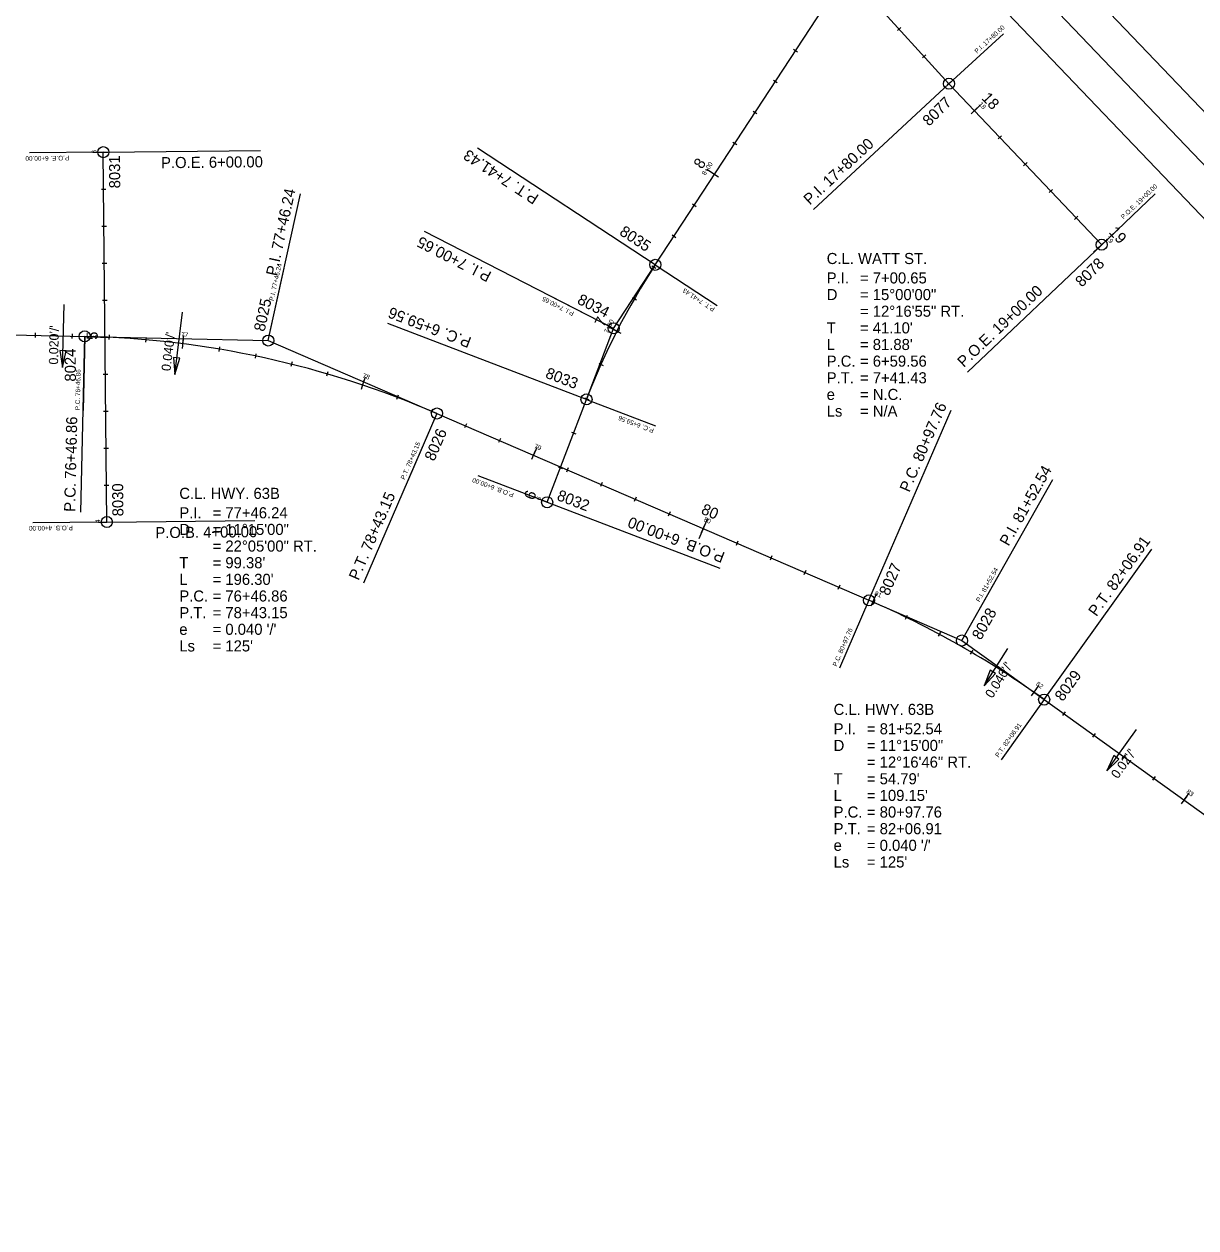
# Model space of a CAD drawing. Extents: x 1708585 to 1714116, y 541444 to 545437.
# Drawn here: x 1712182 to 1712816, y 542879 to 543530 of the extents above; entities that cross this region are included whole.
import ezdxf

# ---------------------------------------------------------------- set-up
doc = ezdxf.new("R2010")
doc.units = 0
for name, color, linetype in [('CL_Highway_2', 7, 'Continuous'), ('CL_Highway_2_40_PText', 7, 'Continuous'), ('CL_Highway_2_40_Sta', 7, 'Continuous'), ('CL_Highway_2_PText', 7, 'Continuous'), ('CL_Highway_2_Sta', 7, 'Continuous'), ('CL_Highway_2_Tangent', 7, 'Continuous'), ('CL_Railroad', 7, 'Continuous'), ('CL_XS_1', 7, 'Continuous'), ('CL_XS_1_40_PText', 7, 'Continuous'), ('CL_XS_1_40_Sta', 7, 'Continuous'), ('CL_XS_1_PText', 7, 'Continuous'), ('CL_XS_1_Sta', 7, 'Continuous'), ('CL_XS_1_Sta_Minor_Text', 7, 'Continuous'), ('CL_XS_1_Tangent', 7, 'Continuous'), ('CL_XS_2', 7, 'Continuous'), ('CL_XS_2_40_PText', 7, 'Continuous'), ('CL_XS_2_40_Sta', 7, 'Continuous'), ('CL_XS_2_PText', 7, 'Continuous'), ('CL_XS_2_Sta', 7, 'Continuous'), ('CL_XS_3', 7, 'Continuous'), ('CL_XS_3_40_PText', 7, 'Continuous'), ('CL_XS_3_40_Sta', 7, 'Continuous'), ('CL_XS_3_PText', 7, 'Continuous'), ('CL_XS_3_Sta', 7, 'Continuous'), ('CL_XS_3_Sta_Minor_Text', 7, 'Continuous'), ('CurveData_100', 7, 'Continuous'), ('Point_CL_Highway_2', 7, 'Continuous'), ('Point_CL_XS_1', 7, 'Continuous'), ('Point_CL_XS_2', 7, 'Continuous'), ('Point_CL_XS_3', 7, 'Continuous'), ('Point_Number', 7, 'Continuous'), ('R_SE_Slope', 7, 'Continuous')]:
    doc.layers.add(name, color=color, linetype=linetype)

msp = doc.modelspace()

# ---------------------------------------------------------------- linework, layer by layer
at = {"layer": 'CL_Highway_2'}
for p, q in [((1712066.88, 543364.6), (1712214.97, 543361.25)), ((1712405.55, 543319.57), (1712639.25, 543218.55)), ((1712734.05, 543164.87), (1712890.94, 543052.31))]:
    msp.add_line(p, q, dxfattribs=at)
for centre, start, end in [((1712203.46, 542852.08), 66.62237, 88.70571), ((1712437.17, 542751.06), 54.3428, 66.62237)]:
    msp.add_arc(centre, 509.3, start, end, dxfattribs=at)
at = {"layer": 'CL_Highway_2_40_PText'}
for points in [[(1712314.32, 543359.01), (1712322.87, 543398.08)], [(1712214.97, 543361.25), (1712214.06, 543321.26)], [(1712405.55, 543319.57), (1712389.67, 543282.86)], [(1712689.54, 543196.81), (1712709.25, 543231.62)], [(1712639.25, 543218.55), (1712623.38, 543181.83)], [(1712734.05, 543164.87), (1712710.73, 543132.37)]]:
    msp.add_lwpolyline(points, dxfattribs=at)
at = {"layer": 'CL_Highway_2_40_Sta'}
for points in [[(1712188.15, 543363.11), (1712188.09, 543360.61)], [(1712208.14, 543362.66), (1712208.08, 543360.16)], [(1712228.16, 543362.03), (1712228.04, 543359.54)], [(1712248.16, 543360.67), (1712247.95, 543358.18)], [(1712268.25, 543359.76), (1712267.62, 543354.8)], [(1712287.93, 543355.59), (1712287.52, 543353.13)], [(1712307.63, 543351.89), (1712307.12, 543349.44)], [(1712327.17, 543347.42), (1712326.57, 543344.99)], [(1712346.53, 543342.18), (1712345.82, 543339.78)], [(1712366.05, 543337.37), (1712364.46, 543332.63)], [(1712384.54, 543329.44), (1712383.65, 543327.1)], [(1712403.14, 543321.96), (1712402.16, 543319.66)], [(1712421.51, 543314.03), (1712420.51, 543311.74)], [(1712439.87, 543306.1), (1712438.87, 543303.8)], [(1712458.72, 543299.31), (1712456.74, 543294.72)], [(1712476.58, 543290.23), (1712475.59, 543287.93)], [(1712494.94, 543282.29), (1712493.95, 543280)], [(1712513.3, 543274.36), (1712512.31, 543272.06)], [(1712531.66, 543266.42), (1712530.66, 543264.13)], [(1712550.51, 543259.63), (1712548.53, 543255.04)], [(1712568.37, 543250.55), (1712567.38, 543248.25)], [(1712586.73, 543242.61), (1712585.74, 543240.32)], [(1712605.09, 543234.68), (1712604.1, 543232.38)], [(1712623.45, 543226.74), (1712622.45, 543224.45)], [(1712642.31, 543219.94), (1712640.31, 543215.36)], [(1712660.01, 543210.4), (1712658.92, 543208.15)], [(1712677.88, 543201.3), (1712676.7, 543199.1)], [(1712695.37, 543191.5), (1712694.1, 543189.35)], [(1712712.46, 543181.03), (1712711.11, 543178.92)], [(1712729.84, 543170.91), (1712726.98, 543166.81)], [(1712745.42, 543158.26), (1712743.96, 543156.23)], [(1712761.67, 543146.6), (1712760.21, 543144.57)], [(1712777.92, 543134.94), (1712776.46, 543132.91)], [(1712794.17, 543123.28), (1712792.71, 543121.25)], [(1712811.15, 543112.64), (1712808.23, 543108.58)]]:
    msp.add_lwpolyline(points, dxfattribs=at)
at = {"layer": 'CL_Highway_2_PText'}
for points in [[(1712314.32, 543359.01), (1712331.69, 543438.42)], [(1712212.82, 543266.27), (1712214.97, 543361.25)], [(1712639.25, 543218.55), (1712683.69, 543321.35)], [(1712405.55, 543319.57), (1712365.87, 543227.78)], [(1712689.54, 543196.81), (1712738.81, 543283.83)], [(1712734.05, 543164.87), (1712792.35, 543246.12)]]:
    msp.add_lwpolyline(points, dxfattribs=at)
at = {"layer": 'CL_Highway_2_Sta'}
for points in [[(1712268.51, 543361.75), (1712267.94, 543357.28)], [(1712366.69, 543339.26), (1712365.26, 543335)], [(1712459.51, 543301.15), (1712457.73, 543297.02)], [(1712551.9, 543262.84), (1712547.14, 543251.83)], [(1712643.11, 543221.78), (1712641.31, 543217.65)], [(1712730.99, 543172.55), (1712728.41, 543168.86)], [(1712812.31, 543114.26), (1712809.69, 543110.61)]]:
    msp.add_lwpolyline(points, dxfattribs=at)
at = {"layer": 'CL_Highway_2_Tangent'}
for points in [[(1712214.97, 543361.25), (1712314.32, 543359.01), (1712405.55, 543319.57)], [(1712642, 543217.36), (1712689.54, 543196.81), (1712734.05, 543164.87)]]:
    msp.add_lwpolyline(points, dxfattribs=at)
at = {"layer": 'CL_Railroad'}
for p, q in [((1710952.7, 545436.87), (1713371.13, 542906.81)), ((1710938.24, 545423.05), (1713356.67, 542892.99)), ((1710923.78, 545409.23), (1713342.21, 542879.17))]:
    msp.add_line(p, q, dxfattribs=at)
at = {"layer": 'CL_XS_1'}
for p, q in [((1712523.65, 543399.96), (1712715.52, 543692.96)), ((1712465.17, 543271.57), (1712486.45, 543327.19))]:
    msp.add_line(p, q, dxfattribs=at)
msp.add_arc((1712843.2, 543190.7), 381.97, 146.78172, 159.06363, dxfattribs=at)
at = {"layer": 'CL_XS_1_40_PText'}
for points in [[(1712523.65, 543399.96), (1712557.11, 543378.05)], [(1712501.13, 543365.58), (1712465.52, 543383.78)], [(1712486.45, 543327.19), (1712523.81, 543312.9)], [(1712465.17, 543271.57), (1712427.81, 543285.86)]]:
    msp.add_lwpolyline(points, dxfattribs=at)
at = {"layer": 'CL_XS_1_40_Sta'}
for points in [[(1712598.51, 543516.57), (1712600.6, 543515.2)], [(1712587.56, 543499.83), (1712589.65, 543498.46)], [(1712576.6, 543483.1), (1712578.69, 543481.73)], [(1712565.64, 543466.37), (1712567.74, 543465)], [(1712553.64, 543450.32), (1712557.82, 543447.58)], [(1712543.73, 543432.91), (1712545.82, 543431.54)], [(1712532.77, 543416.17), (1712534.87, 543414.81)], [(1712521.82, 543399.44), (1712523.91, 543398.08)], [(1712511.33, 543382.33), (1712513.5, 543381.08)], [(1712500.65, 543365.27), (1712505.1, 543363)], [(1712493.12, 543346.59), (1712495.4, 543345.58)], [(1712485.44, 543328.06), (1712487.78, 543327.16)], [(1712478.29, 543309.38), (1712480.63, 543308.48)], [(1712471.15, 543290.7), (1712473.48, 543289.8)], [(1712462.83, 543272.46), (1712467.5, 543270.68)]]:
    msp.add_lwpolyline(points, dxfattribs=at)
at = {"layer": 'CL_XS_1_PText'}
for points in [[(1712523.65, 543399.96), (1712427.44, 543462.96)], [(1712501.13, 543365.58), (1712398.74, 543417.92)], [(1712486.45, 543327.19), (1712379.04, 543368.29)], [(1712465.17, 543271.57), (1712558.57, 543235.84)]]:
    msp.add_lwpolyline(points, dxfattribs=at)
at = {"layer": 'CL_XS_1_Sta'}
for points in [[(1712551.55, 543451.69), (1712555.73, 543448.95)], [(1712498.42, 543366.4), (1712502.87, 543364.13)], [(1712460.97, 543273.18), (1712465.17, 543271.57)]]:
    msp.add_lwpolyline(points, dxfattribs=at)
at = {"layer": 'CL_XS_1_Tangent'}
for p, q in [((1712501.13, 543365.58), (1712523.65, 543399.96)), ((1712486.45, 543327.19), (1712501.13, 543365.58))]:
    msp.add_line(p, q, dxfattribs=at)
at = {"layer": 'CL_XS_2'}
msp.add_line((1712226.97, 543260.89), (1712225.04, 543460.88), dxfattribs=at)
at = {"layer": 'CL_XS_2_40_PText'}
for points in [[(1712225.04, 543460.88), (1712185.05, 543460.49)], [(1712226.97, 543260.89), (1712186.97, 543260.5)]]:
    msp.add_lwpolyline(points, dxfattribs=at)
at = {"layer": 'CL_XS_2_40_Sta'}
for points in [[(1712222.54, 543460.85), (1712227.54, 543460.9)], [(1712223.99, 543440.87), (1712226.49, 543440.89)], [(1712224.18, 543420.87), (1712226.68, 543420.89)], [(1712224.37, 543400.87), (1712226.87, 543400.89)], [(1712224.56, 543380.87), (1712227.06, 543380.89)], [(1712223.51, 543360.86), (1712228.51, 543360.91)], [(1712224.95, 543340.87), (1712227.45, 543340.89)], [(1712225.14, 543320.87), (1712227.64, 543320.9)], [(1712225.33, 543300.87), (1712227.83, 543300.9)], [(1712225.53, 543280.87), (1712228.03, 543280.9)], [(1712224.47, 543260.86), (1712229.47, 543260.91)]]:
    msp.add_lwpolyline(points, dxfattribs=at)
at = {"layer": 'CL_XS_2_PText'}
for points in [[(1712225.04, 543460.88), (1712310.04, 543461.69)], [(1712226.97, 543260.89), (1712306.96, 543261.66)]]:
    msp.add_lwpolyline(points, dxfattribs=at)
at = {"layer": 'CL_XS_2_Sta'}
for points in [[(1712220.54, 543460.83), (1712225.04, 543460.88)], [(1712220, 543360.82), (1712232, 543360.94)], [(1712222.47, 543260.84), (1712226.97, 543260.89)]]:
    msp.add_lwpolyline(points, dxfattribs=at)
at = {"layer": 'CL_XS_3'}
for p, q in [((1712561.4, 543631), (1712682.55, 543497.88)), ((1712682.55, 543497.88), (1712765.17, 543410.85))]:
    msp.add_line(p, q, dxfattribs=at)
at = {"layer": 'CL_XS_3_40_PText'}
for points in [[(1712682.55, 543497.88), (1712712.13, 543524.8)], [(1712765.17, 543410.85), (1712794.18, 543438.39)]]:
    msp.add_lwpolyline(points, dxfattribs=at)
at = {"layer": 'CL_XS_3_40_Sta'}
for points in [[(1712656.55, 543528.3), (1712654.7, 543526.62)], [(1712670.01, 543513.51), (1712668.17, 543511.83)], [(1712683.48, 543498.72), (1712681.63, 543497.03)], [(1712698.14, 543485.09), (1712694.51, 543481.65)], [(1712711, 543469.73), (1712709.19, 543468.01)], [(1712724.77, 543455.22), (1712722.96, 543453.5)], [(1712738.54, 543440.72), (1712736.73, 543439)], [(1712752.31, 543426.21), (1712750.5, 543424.49)], [(1712766.99, 543412.57), (1712763.36, 543409.13)]]:
    msp.add_lwpolyline(points, dxfattribs=at)
at = {"layer": 'CL_XS_3_PText'}
for points in [[(1712682.55, 543497.88), (1712609.31, 543429.79)], [(1712765.17, 543410.85), (1712692.65, 543342)]]:
    msp.add_lwpolyline(points, dxfattribs=at)
at = {"layer": 'CL_XS_3_Sta'}
for points in [[(1712699.59, 543486.47), (1712696.32, 543483.37)], [(1712769.53, 543414.98), (1712760.82, 543406.72)]]:
    msp.add_lwpolyline(points, dxfattribs=at)
at = {"layer": 'Point_CL_Highway_2'}
for centre in [(1712214.97, 543361.25), (1712314.32, 543359.01), (1712405.55, 543319.57), (1712639.25, 543218.55), (1712689.54, 543196.81), (1712734.05, 543164.87)]:
    msp.add_circle(centre, 3, dxfattribs=at)
at = {"layer": 'Point_CL_XS_1'}
for centre in [(1712523.65, 543399.96), (1712501.13, 543365.58), (1712486.45, 543327.19), (1712465.17, 543271.57)]:
    msp.add_circle(centre, 3, dxfattribs=at)
at = {"layer": 'Point_CL_XS_2'}
for centre in [(1712225.04, 543460.88), (1712226.97, 543260.89)]:
    msp.add_circle(centre, 3, dxfattribs=at)
at = {"layer": 'Point_CL_XS_3'}
for centre in [(1712682.55, 543497.88), (1712765.17, 543410.85)]:
    msp.add_circle(centre, 3, dxfattribs=at)
at = {"layer": 'R_SE_Slope'}
for p, q in [((1712203.02, 543344.52), (1712203.79, 543378.51)), ((1712263.67, 543340.69), (1712267.82, 543374.43)), ((1712701.56, 543172.25), (1712714.32, 543192.57)), ((1712767.9, 543126.28), (1712783.94, 543148.63))]:
    msp.add_line(p, q, dxfattribs=at)
for points in [[(1712204.91, 543353.47), (1712201.54, 543353.55), (1712203.02, 543344.51)], [(1712266.44, 543349.41), (1712263.09, 543349.82), (1712263.67, 543340.69)], [(1712707.78, 543178.97), (1712704.92, 543180.77), (1712701.56, 543172.25)], [(1712774.52, 543132.61), (1712771.78, 543134.58), (1712767.9, 543126.28)]]:
    msp.add_lwpolyline(points, close=True, dxfattribs=at)

# ---------------------------------------------------------------- texts
at = {"layer": 'CL_Highway_2_40_PText'}
for s, rotation, p in [('P.I. 77+46.24', 77.66404, (1712317.18, 543380.27)), ('P.C. 76+46.86', 88.70571, (1712212.31, 543321.3)), ('P.T. 78+43.15', 66.62237, (1712388.07, 543283.55)), ('P.I. 81+52.54', 60.48258, (1712699.16, 543217.35)), ('P.C. 80+97.76', 66.62237, (1712621.77, 543182.53)), ('P.T. 82+06.91', 54.3428, (1712709.31, 543133.39))]:
    msp.add_text(s, height=2.5, rotation=rotation, dxfattribs=at).set_placement(p)
at = {"layer": 'CL_Highway_2_40_Sta'}
for s, rotation, p in [('77', 352.72698, (1712266.96, 543361.19)), ('78', 341.47698, (1712365.06, 543339.02)), ('79', 336.62237, (1712457.86, 543301.04)), ('80', 336.62237, (1712549.58, 543261.39)), ('81', 336.36994, (1712641.99, 543221.45)), ('82', 325.11994, (1712729.36, 543172.78)), ('83', 324.3428, (1712810.69, 543114.51))]:
    msp.add_text(s, height=2.5, rotation=rotation, dxfattribs=at).set_placement(p)
at = {"layer": 'CL_Highway_2_PText'}
for s, rotation, p in [('P.I. 77+46.24', 77.66404, (1712318.82, 543393.6)), ('P.C. 80+97.76', 66.62237, (1712661.08, 543276.61)), ('P.C. 76+46.86', 88.70571, (1712209.82, 543266.34)), ('P.I. 81+52.54', 60.48258, (1712714.78, 543247.49)), ('P.T. 78+43.15', 66.62237, (1712363.11, 543228.97)), ('P.T. 82+06.91', 54.3428, (1712762.32, 543209.42))]:
    msp.add_text(s, height=6, rotation=rotation, dxfattribs=at).set_placement(p)
at = {"layer": 'CL_Highway_2_Sta'}
msp.add_text('80', height=6, rotation=336.62237, dxfattribs=at).set_placement((1712548.02, 543265.61))
msp.add_text('80', height=6, rotation=336.62237, dxfattribs=at).set_placement((1712548.02, 543265.61))
at = {"layer": 'CL_XS_1_40_PText'}
for s, rotation, p in [('P.T. 7+41.43', 146.78172, (1712556.15, 543376.58)), ('P.I. 7+00.65', 152.92268, (1712479.98, 543374.43)), ('P.C. 6+59.56', 159.06363, (1712523.18, 543311.27)), ('P.O.B. 6+00.00', 159.06363, (1712447.38, 543276.5))]:
    msp.add_text(s, height=2.5, rotation=rotation, dxfattribs=at).set_placement(p)
at = {"layer": 'CL_XS_1_40_Sta'}
for s, rotation, p in [('8+00', 56.78172, (1712550.68, 543448.08)), ('7+00', 62.9969, (1712497.94, 543362.71)), ('6', 69.06363, (1712461.44, 543272.33))]:
    msp.add_text(s, height=2.5, rotation=rotation, dxfattribs=at).set_placement(p)
at = {"layer": 'CL_XS_1_PText'}
for s, rotation, p in [('P.T. 7+41.43', 146.78172, (1712461.11, 543437.33)), ('P.I. 7+00.65', 152.92268, (1712435.51, 543395.75)), ('P.C. 6+59.56', 159.06363, (1712424.65, 543360.47)), ('P.O.B. 6+00.00', 159.06363, (1712561.78, 543244.24))]:
    msp.add_text(s, height=6, rotation=rotation, dxfattribs=at).set_placement(p)
at = {"layer": 'CL_XS_1_Sta_Minor_Text'}
for s, rotation, p in [('8', 56.78172, (1712548.94, 543451.37)), ('7', 62.9969, (1712495.86, 543365.8)), ('6', 69.06363, (1712457.96, 543272.33))]:
    msp.add_text(s, height=6, rotation=rotation, dxfattribs=at).set_placement(p)
at = {"layer": 'CL_XS_2_40_PText'}
for s, p in [('P.O.E. 6+00.00', (1712206.59, 543458.95)), ('P.O.B. 4+00.00', (1712208.51, 543258.96))]:
    msp.add_text(s, height=2.5, rotation=180.55135, dxfattribs=at).set_placement(p)
at = {"layer": 'CL_XS_2_40_Sta'}
for s, p in [('6', (1712221.3, 543460.22)), ('5', (1712222.26, 543360.28)), ('4', (1712223.22, 543260.28))]:
    msp.add_text(s, height=2.5, rotation=90.55135, dxfattribs=at).set_placement(p)
at = {"layer": 'CL_XS_2_PText'}
for s, p in [('P.O.E. 6+00.00', (1712256.31, 543452.18)), ('P.O.B. 4+00.00', (1712253.23, 543252.14))]:
    msp.add_text(s, height=6, rotation=0.55135, dxfattribs=at).set_placement(p)
at = {"layer": 'CL_XS_2_Sta'}
msp.add_text('5', height=6, rotation=90.55135, dxfattribs=at).set_placement((1712222.02, 543359.43))
at = {"layer": 'CL_XS_3_40_PText'}
for s, rotation, p in [('P.I. 17+80.00', 42.30486, (1712697.74, 543514.06)), ('P.O.E. 19+00.00', 43.51294, (1712776.95, 543424.45))]:
    msp.add_text(s, height=2.5, rotation=rotation, dxfattribs=at).set_placement(p)
at = {"layer": 'CL_XS_3_40_Sta'}
for s, p in [('18', (1712698.42, 543486.6)), ('19', (1712767.27, 543414.09))]:
    msp.add_text(s, height=2.5, rotation=313.51294, dxfattribs=at).set_placement(p)
at = {"layer": 'CL_XS_3_PText'}
for s, rotation, p in [('P.I. 17+80.00', 42.9089, (1712607.27, 543431.99)), ('P.O.E. 19+00.00', 43.51294, (1712690.59, 543344.17))]:
    msp.add_text(s, height=6, rotation=rotation, dxfattribs=at).set_placement(p)
at = {"layer": 'CL_XS_3_Sta_Minor_Text'}
for s, p in [('18', (1712699.85, 543489.82)), ('19', (1712768.69, 543417.31))]:
    msp.add_text(s, height=6, rotation=313.51294, dxfattribs=at).set_placement(p)
at = {"layer": 'CurveData_100'}
for s, p in [('C.L. WATT ST.', (1712616.4, 543400.38)), ('P.I.', (1712616.4, 543389.88)), ('= 7+00.65', (1712634.4, 543389.88)), ('D', (1712616.4, 543380.88)), ('= 15%%d00\'00"', (1712634.4, 543380.88)), ('= 12%%d16\'55" RT.', (1712634.4, 543371.88)), ('T', (1712616.4, 543362.88)), ("= 41.10'", (1712634.4, 543362.88)), ("= 81.88'", (1712634.4, 543353.88)), ('L', (1712616.4, 543353.88)), ('P.C.', (1712616.4, 543344.88)), ('= 6+59.56', (1712634.4, 543344.88)), ('P.T.', (1712616.4, 543335.88)), ('= 7+41.43', (1712634.4, 543335.88)), ('e', (1712616.4, 543326.88)), ('= N.C.', (1712634.4, 543326.88)), ('Ls', (1712616.4, 543317.88)), ('= N/A', (1712634.4, 543317.88)), ('C.L. HWY. 63B', (1712266.16, 543273.38)), ('P.I.', (1712266.16, 543262.88)), ('= 77+46.24', (1712284.16, 543262.88)), ('D', (1712266.16, 543253.88)), ('= 11%%d15\'00"', (1712284.16, 543253.88)), ('= 22%%d05\'00" RT.', (1712284.16, 543244.88)), ('T', (1712266.16, 543235.88)), ("= 99.38'", (1712284.16, 543235.88)), ('L', (1712266.16, 543226.88)), ("= 196.30'", (1712284.16, 543226.88)), ('P.C.', (1712266.16, 543217.88)), ('= 76+46.86', (1712284.16, 543217.88)), ('P.T.', (1712266.16, 543208.88)), ('= 78+43.15', (1712284.16, 543208.88)), ('e', (1712266.16, 543199.88)), ("= 0.040 '/'", (1712284.16, 543199.88)), ('Ls', (1712266.16, 543190.88)), ("= 125'", (1712284.16, 543190.88)), ('C.L. HWY. 63B', (1712620.14, 543156.56)), ('P.I.', (1712620.14, 543146.06)), ('= 81+52.54', (1712638.14, 543146.06)), ('D', (1712620.14, 543137.06)), ('= 11%%d15\'00"', (1712638.14, 543137.06)), ('= 12%%d16\'46" RT.', (1712638.14, 543128.06)), ('T', (1712620.14, 543119.06)), ("= 54.79'", (1712638.14, 543119.06)), ('L', (1712620.14, 543110.06)), ("= 109.15'", (1712638.14, 543110.06)), ('P.C.', (1712620.14, 543101.06)), ('= 80+97.76', (1712638.14, 543101.06)), ('P.T.', (1712620.14, 543092.06)), ('= 82+06.91', (1712638.14, 543092.06)), ('e', (1712620.14, 543083.06)), ("= 0.040 '/'", (1712638.14, 543083.06)), ('Ls', (1712620.14, 543074.06)), ("= 125'", (1712638.14, 543074.06))]:
    msp.add_text(s, height=6, dxfattribs=at).set_placement(p)
at = {"layer": 'Point_Number'}
for s, rotation, p in [('8077', 44.73173, (1712671.81, 543474.57)), ('8031', 90.55135, (1712234.23, 543441.33)), ('8035', 326.78172, (1712503.81, 543416.54)), ('8078', 44.73173, (1712754.44, 543387.54)), ('8025', 77.66404, (1712312.25, 543363.55)), ('8034', 332.92268, (1712480.96, 543379.26)), ('8024', 90.26483, (1712210.22, 543336.82)), ('8033', 339.06363, (1712463.78, 543339.08)), ('8026', 66.62237, (1712404.04, 543293.4)), ('8030', 90.55135, (1712235.94, 543263.97)), ('8032', 339.06363, (1712469.99, 543272.94)), ('8027', 66.62237, (1712649.94, 543220.59)), ('8028', 60.48258, (1712699.79, 543196.66)), ('8029', 54.3428, (1712744.13, 543163.48))]:
    msp.add_text(s, height=6, rotation=rotation, dxfattribs=at).set_placement(p)
at = {"layer": 'R_SE_Slope'}
for s, rotation, p in [("0.020'/'", 88.70571, (1712200.55, 543346)), ("0.040'/'", 82.97588, (1712261.35, 543342.29)), ("0.040'/'", 57.88158, (1712706.01, 543165.23)), ("0.02'/'", 54.3428, (1712773.87, 543121.73))]:
    msp.add_text(s, height=5, rotation=rotation, dxfattribs=at).set_placement(p)

doc.saveas('drawing.dxf')
